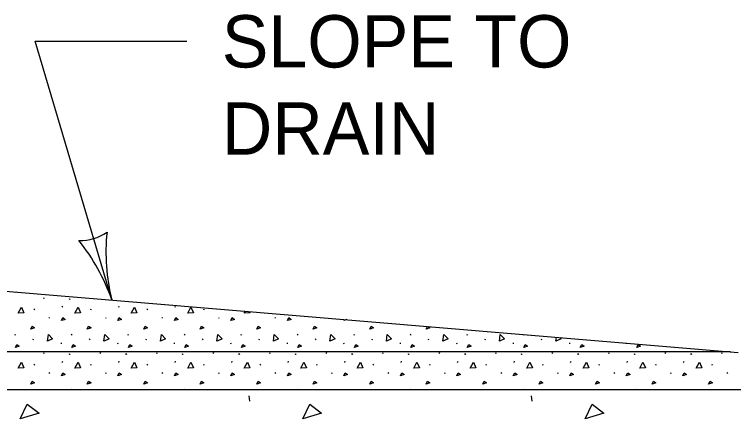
# Model space of a CAD drawing. Extents: x 49991.4 to 50041.6, y 49987.6 to 50011.4.
# Drawn here: x 50026.75 to 50027.575, y 49991.279 to 49991.757 of the extents above; entities that cross this region are included whole.
import ezdxf

# ---------------------------------------------------------------- set-up
doc = ezdxf.new("R2010")
doc.units = 0
for name, color, linetype in [('Level 1', 7, 'Continuous'), ('Level 2', 7, 'Continuous'), ('Level 3', 7, 'Continuous'), ('Level 4', 7, 'Continuous')]:
    doc.layers.add(name, color=color, linetype=linetype)

msp = doc.modelspace()

# ---------------------------------------------------------------- linework, layer by layer
at = {"layer": 'Level 1'}
for p, q in [((50026.14318, 49991.48968), (50027.58032, 49991.36954)), ((50027.01899, 49991.31948), (50027.01967, 49991.31339)), ((50027.34313, 49991.31948), (50027.34381, 49991.31339))]:
    msp.add_line(p, q, dxfattribs=at)
for points in [[(50025.99318, 49991.14695), (50025.99318, 49991.32695), (50027.72873, 49991.32695), (50027.72873, 49991.14695)], [(50026.75661, 49991.29317), (50026.76473, 49991.31009), (50026.77826, 49991.29994), (50026.75661, 49991.29317)], [(50027.08075, 49991.29317), (50027.08887, 49991.31009), (50027.1024, 49991.29994), (50027.08075, 49991.29317)], [(50027.40489, 49991.29317), (50027.41301, 49991.31009), (50027.42654, 49991.29994), (50027.40489, 49991.29317)]]:
    msp.add_lwpolyline(points, dxfattribs=at)
at = {"layer": 'Level 3'}
for p, q in [((50026.86175, 49991.42961), (50026.77384, 49991.72631)), ((50026.77384, 49991.72631), (50026.94792, 49991.72631)), ((50027.57184, 49991.37025), (50026.64808, 49991.37025))]:
    msp.add_line(p, q, dxfattribs=at)
for centre, radius, start, end in [((50026.82532, 49991.55254), 0.05477, 268.64324, 304.3656), ((50027.07733, 49991.48394), 0.22232, 173.96043, 194.14394), ((50026.64189, 49991.35248), 0.233, 19.33173, 38.58158)]:
    msp.add_arc(centre, radius, start, end, dxfattribs=at)
at = {"layer": 'Level 4'}
for p, q in [((50026.7837, 49991.43127), (50026.78424, 49991.43249)), ((50026.81279, 49991.43127), (50026.81333, 49991.43046)), ((50026.81333, 49991.43096), (50026.81388, 49991.43015)), ((50026.80481, 49991.42124), (50026.80535, 49991.42246)), ((50026.86964, 49991.42124), (50026.87018, 49991.42246)), ((50026.93446, 49991.42124), (50026.935, 49991.42246)), ((50026.77273, 49991.41813), (50026.77327, 49991.41935)), ((50026.83756, 49991.41813), (50026.8381, 49991.41935)), ((50026.90239, 49991.41813), (50026.90293, 49991.41935)), ((50026.96722, 49991.41813), (50026.96776, 49991.41935)), ((50026.78965, 49991.40947), (50026.79019, 49991.40865)), ((50026.85448, 49991.40947), (50026.85502, 49991.40865)), ((50026.91931, 49991.40947), (50026.91985, 49991.40865)), ((50026.98413, 49991.40947), (50026.98467, 49991.40865)), ((50027.04896, 49991.40947), (50027.0495, 49991.40865)), ((50026.75081, 49991.3893), (50026.75135, 49991.39052)), ((50026.81564, 49991.3893), (50026.81618, 49991.39052)), ((50026.88046, 49991.3893), (50026.88101, 49991.39052)), ((50026.94529, 49991.3893), (50026.94583, 49991.39052)), ((50027.01012, 49991.3893), (50027.01066, 49991.39052)), ((50027.07495, 49991.3893), (50027.07549, 49991.39052)), ((50027.13977, 49991.3893), (50027.14032, 49991.39052)), ((50027.2046, 49991.3893), (50027.20514, 49991.39052)), ((50027.26943, 49991.3893), (50027.26997, 49991.39052)), ((50027.33426, 49991.3893), (50027.3346, 49991.39008)), ((50026.77138, 49991.38375), (50026.77192, 49991.38497)), ((50026.83621, 49991.38375), (50026.83675, 49991.38497)), ((50026.90104, 49991.38375), (50026.90158, 49991.38497)), ((50026.96586, 49991.38375), (50026.9664, 49991.38497)), ((50027.03069, 49991.38375), (50027.03123, 49991.38497)), ((50027.09552, 49991.38375), (50027.09606, 49991.38497)), ((50027.16035, 49991.38375), (50027.16089, 49991.38497)), ((50027.22517, 49991.38375), (50027.22571, 49991.38497)), ((50027.29, 49991.38375), (50027.29054, 49991.38497)), ((50027.35483, 49991.38375), (50027.35537, 49991.38497)), ((50026.80356, 49991.38035), (50026.80369, 49991.37914)), ((50026.86838, 49991.38035), (50026.86852, 49991.37914)), ((50026.93321, 49991.38035), (50026.93335, 49991.37914)), ((50026.99804, 49991.38035), (50026.99817, 49991.37914)), ((50027.06287, 49991.38035), (50027.063, 49991.37914)), ((50027.12769, 49991.38035), (50027.12783, 49991.37914)), ((50027.19252, 49991.38035), (50027.19266, 49991.37914)), ((50027.25735, 49991.38035), (50027.25748, 49991.37914)), ((50027.32218, 49991.38035), (50027.32231, 49991.37914)), ((50027.387, 49991.38035), (50027.38714, 49991.37914)), ((50027.45184, 49991.38028), (50027.45197, 49991.37914)), ((50026.7837, 49991.36806), (50026.78424, 49991.36927)), ((50026.81279, 49991.36806), (50026.81333, 49991.36724)), ((50026.81333, 49991.36775), (50026.81388, 49991.36693)), ((50026.84852, 49991.36806), (50026.84906, 49991.36927)), ((50026.87762, 49991.36806), (50026.87816, 49991.36724)), ((50026.87816, 49991.36775), (50026.8787, 49991.36693)), ((50026.91335, 49991.36806), (50026.91389, 49991.36927)), ((50026.94245, 49991.36806), (50026.94299, 49991.36724)), ((50026.94299, 49991.36775), (50026.94353, 49991.36693)), ((50026.97818, 49991.36806), (50026.97872, 49991.36927)), ((50027.00728, 49991.36806), (50027.00782, 49991.36724)), ((50027.00782, 49991.36775), (50027.00836, 49991.36693)), ((50027.04301, 49991.36806), (50027.04355, 49991.36927)), ((50027.0721, 49991.36806), (50027.07264, 49991.36724)), ((50027.07264, 49991.36775), (50027.07319, 49991.36693)), ((50027.10783, 49991.36806), (50027.10837, 49991.36927)), ((50027.13693, 49991.36806), (50027.13747, 49991.36724)), ((50027.13747, 49991.36775), (50027.13801, 49991.36693)), ((50027.17266, 49991.36806), (50027.1732, 49991.36927)), ((50027.20176, 49991.36806), (50027.2023, 49991.36724)), ((50027.2023, 49991.36775), (50027.20284, 49991.36693)), ((50027.23749, 49991.36806), (50027.23803, 49991.36927)), ((50027.26659, 49991.36806), (50027.26713, 49991.36724)), ((50027.26713, 49991.36775), (50027.26767, 49991.36693)), ((50027.30232, 49991.36806), (50027.30286, 49991.36927)), ((50027.33141, 49991.36806), (50027.33195, 49991.36724)), ((50027.33195, 49991.36775), (50027.3325, 49991.36693)), ((50027.36714, 49991.36806), (50027.36768, 49991.36927)), ((50027.39624, 49991.36806), (50027.39678, 49991.36724)), ((50027.39678, 49991.36775), (50027.39732, 49991.36693)), ((50027.43197, 49991.36806), (50027.43251, 49991.36927)), ((50027.46107, 49991.36806), (50027.46161, 49991.36724)), ((50027.46161, 49991.36775), (50027.46215, 49991.36693)), ((50027.4968, 49991.36806), (50027.49734, 49991.36927)), ((50027.5259, 49991.36806), (50027.52644, 49991.36724)), ((50027.52644, 49991.36775), (50027.52698, 49991.36693)), ((50027.56163, 49991.36806), (50027.56217, 49991.36927)), ((50026.77273, 49991.35491), (50026.77327, 49991.35613)), ((50026.80481, 49991.35802), (50026.80535, 49991.35924)), ((50026.83756, 49991.35491), (50026.8381, 49991.35613)), ((50026.86964, 49991.35802), (50026.87018, 49991.35924)), ((50026.90239, 49991.35491), (50026.90293, 49991.35613)), ((50026.93446, 49991.35802), (50026.935, 49991.35924)), ((50026.96722, 49991.35491), (50026.96776, 49991.35613)), ((50026.99929, 49991.35802), (50026.99983, 49991.35924)), ((50027.03204, 49991.35491), (50027.03258, 49991.35613)), ((50027.06412, 49991.35802), (50027.06466, 49991.35924)), ((50027.09687, 49991.35491), (50027.09741, 49991.35613)), ((50027.12895, 49991.35802), (50027.12949, 49991.35924)), ((50027.1617, 49991.35491), (50027.16224, 49991.35613)), ((50027.19377, 49991.35802), (50027.19431, 49991.35924)), ((50027.22653, 49991.35491), (50027.22707, 49991.35613)), ((50027.2586, 49991.35802), (50027.25914, 49991.35924)), ((50027.29135, 49991.35491), (50027.29189, 49991.35613)), ((50027.32343, 49991.35802), (50027.32397, 49991.35924)), ((50027.35618, 49991.35491), (50027.35672, 49991.35613)), ((50027.38826, 49991.35802), (50027.3888, 49991.35924)), ((50027.42101, 49991.35491), (50027.42155, 49991.35613)), ((50027.45308, 49991.35802), (50027.45362, 49991.35924)), ((50027.48584, 49991.35491), (50027.48638, 49991.35613)), ((50027.51791, 49991.35802), (50027.51845, 49991.35924)), ((50027.55066, 49991.35491), (50027.5512, 49991.35613)), ((50026.78965, 49991.34625), (50026.79019, 49991.34544)), ((50026.85448, 49991.34625), (50026.85502, 49991.34544)), ((50026.91931, 49991.34625), (50026.91985, 49991.34544)), ((50026.98413, 49991.34625), (50026.98467, 49991.34544)), ((50027.04896, 49991.34625), (50027.0495, 49991.34544)), ((50027.11379, 49991.34625), (50027.11433, 49991.34544)), ((50027.17862, 49991.34625), (50027.17916, 49991.34544)), ((50027.24344, 49991.34625), (50027.24398, 49991.34544)), ((50027.30827, 49991.34625), (50027.30881, 49991.34544)), ((50027.3731, 49991.34625), (50027.37364, 49991.34544)), ((50027.43793, 49991.34625), (50027.43847, 49991.34544)), ((50027.50275, 49991.34625), (50027.50329, 49991.34544)), ((50027.56758, 49991.34625), (50027.56812, 49991.34544)), ((50026.75119, 49991.32695), (50026.75135, 49991.3273)), ((50026.81602, 49991.32695), (50026.81618, 49991.3273)), ((50026.88085, 49991.32695), (50026.88101, 49991.3273)), ((50026.94567, 49991.32695), (50026.94583, 49991.3273)), ((50027.0105, 49991.32695), (50027.01066, 49991.3273)), ((50027.07533, 49991.32695), (50027.07549, 49991.3273)), ((50027.14016, 49991.32695), (50027.14032, 49991.3273)), ((50027.20498, 49991.32695), (50027.20514, 49991.3273)), ((50027.26981, 49991.32695), (50027.26997, 49991.3273)), ((50027.33464, 49991.32695), (50027.3348, 49991.3273)), ((50027.39947, 49991.32695), (50027.39963, 49991.3273)), ((50027.46429, 49991.32695), (50027.46445, 49991.3273)), ((50027.52912, 49991.32695), (50027.52928, 49991.3273))]:
    msp.add_line(p, q, dxfattribs=at)
for points in [[(50026.75108, 49991.43831), (50026.75133, 49991.43884)], [(50026.75247, 49991.43875), (50026.75108, 49991.43831)], [(50026.75446, 49991.41447), (50026.75812, 49991.42138), (50026.76096, 49991.41502), (50026.7546, 49991.41447)], [(50026.81929, 49991.41447), (50026.82294, 49991.42138), (50026.82579, 49991.41502), (50026.81943, 49991.41447)], [(50026.88412, 49991.41447), (50026.88777, 49991.42138), (50026.89061, 49991.41502), (50026.88425, 49991.41447)], [(50026.94895, 49991.41447), (50026.9526, 49991.42138), (50026.95544, 49991.41502), (50026.94908, 49991.41447)], [(50027.01377, 49991.41447), (50027.015, 49991.4168)], [(50027.01965, 49991.41641), (50027.02027, 49991.41502), (50027.01391, 49991.41447)], [(50026.80386, 49991.40595), (50026.80548, 49991.40933), (50026.80819, 49991.4073), (50026.80386, 49991.40595)], [(50026.86869, 49991.40595), (50026.87031, 49991.40933), (50026.87302, 49991.4073), (50026.86869, 49991.40595)], [(50026.93352, 49991.40595), (50026.93514, 49991.40933), (50026.93785, 49991.4073), (50026.93352, 49991.40595)], [(50026.99834, 49991.40595), (50026.99997, 49991.40933), (50027.00267, 49991.4073), (50026.99834, 49991.40595)], [(50027.06317, 49991.40595), (50027.06479, 49991.40933), (50027.0675, 49991.4073), (50027.06317, 49991.40595)], [(50027.128, 49991.40595), (50027.12865, 49991.4073)], [(50027.13155, 49991.40706), (50027.128, 49991.40595)], [(50026.7687, 49991.39627), (50026.77032, 49991.39966), (50026.77303, 49991.39763), (50026.7687, 49991.39627)], [(50026.83353, 49991.39627), (50026.83515, 49991.39966), (50026.83786, 49991.39763), (50026.83353, 49991.39627)], [(50026.89836, 49991.39627), (50026.89998, 49991.39966), (50026.90269, 49991.39763), (50026.89836, 49991.39627)], [(50026.96318, 49991.39627), (50026.96481, 49991.39966), (50026.96751, 49991.39763), (50026.96318, 49991.39627)], [(50027.02801, 49991.39627), (50027.02963, 49991.39966), (50027.03234, 49991.39763), (50027.02801, 49991.39627)], [(50027.09284, 49991.39627), (50027.09446, 49991.39966), (50027.09717, 49991.39763), (50027.09284, 49991.39627)], [(50027.15767, 49991.39627), (50027.15929, 49991.39966), (50027.162, 49991.39763), (50027.15767, 49991.39627)], [(50027.22249, 49991.39627), (50027.22396, 49991.39933)], [(50027.22462, 49991.39928), (50027.22682, 49991.39763), (50027.22249, 49991.39627)], [(50026.78784, 49991.38235), (50026.78892, 49991.39009), (50026.79376, 49991.38508), (50026.78797, 49991.3824)], [(50026.85267, 49991.38235), (50026.85374, 49991.39009), (50026.85859, 49991.38508), (50026.8528, 49991.3824)], [(50026.9175, 49991.38235), (50026.91857, 49991.39009), (50026.92342, 49991.38508), (50026.91763, 49991.3824)], [(50026.98233, 49991.38235), (50026.9834, 49991.39009), (50026.98825, 49991.38508), (50026.98245, 49991.3824)], [(50027.04715, 49991.38235), (50027.04823, 49991.39009), (50027.05307, 49991.38508), (50027.04728, 49991.3824)], [(50027.11198, 49991.38235), (50027.11305, 49991.39009), (50027.1179, 49991.38508), (50027.11211, 49991.3824)], [(50027.17681, 49991.38235), (50027.17788, 49991.39009), (50027.18273, 49991.38508), (50027.17694, 49991.3824)], [(50027.24164, 49991.38235), (50027.24271, 49991.39009), (50027.24756, 49991.38508), (50027.24176, 49991.3824)], [(50027.30646, 49991.38235), (50027.30754, 49991.39009), (50027.31238, 49991.38508), (50027.30659, 49991.3824)], [(50027.37129, 49991.38235), (50027.37193, 49991.38696)], [(50027.3757, 49991.38665), (50027.37721, 49991.38508), (50027.37142, 49991.3824)], [(50026.75108, 49991.37509), (50026.7527, 49991.37848), (50026.75541, 49991.37645), (50026.75108, 49991.37509)], [(50026.81591, 49991.37509), (50026.81753, 49991.37848), (50026.82024, 49991.37645), (50026.81591, 49991.37509)], [(50026.88074, 49991.37509), (50026.88236, 49991.37848), (50026.88507, 49991.37645), (50026.88074, 49991.37509)], [(50026.94556, 49991.37509), (50026.94719, 49991.37848), (50026.94989, 49991.37645), (50026.94556, 49991.37509)], [(50027.01039, 49991.37509), (50027.01201, 49991.37848), (50027.01472, 49991.37645), (50027.01039, 49991.37509)], [(50027.07522, 49991.37509), (50027.07684, 49991.37848), (50027.07955, 49991.37645), (50027.07522, 49991.37509)], [(50027.14005, 49991.37509), (50027.14167, 49991.37848), (50027.14438, 49991.37645), (50027.14005, 49991.37509)], [(50027.20487, 49991.37509), (50027.2065, 49991.37848), (50027.2092, 49991.37645), (50027.20487, 49991.37509)], [(50027.2697, 49991.37509), (50027.27132, 49991.37848), (50027.27403, 49991.37645), (50027.2697, 49991.37509)], [(50027.33453, 49991.37509), (50027.33615, 49991.37848), (50027.33886, 49991.37645), (50027.33453, 49991.37509)], [(50027.39936, 49991.37509), (50027.40098, 49991.37848), (50027.40369, 49991.37645), (50027.39936, 49991.37509)], [(50027.46418, 49991.37509), (50027.46581, 49991.37848), (50027.46851, 49991.37645), (50027.46418, 49991.37509)], [(50026.75446, 49991.35126), (50026.75812, 49991.35816), (50026.76096, 49991.3518), (50026.7546, 49991.35126)], [(50026.81929, 49991.35126), (50026.82294, 49991.35816), (50026.82579, 49991.3518), (50026.81943, 49991.35126)], [(50026.88412, 49991.35126), (50026.88777, 49991.35816), (50026.89061, 49991.3518), (50026.88425, 49991.35126)], [(50026.94895, 49991.35126), (50026.9526, 49991.35816), (50026.95544, 49991.3518), (50026.94908, 49991.35126)], [(50027.01377, 49991.35126), (50027.01743, 49991.35816), (50027.02027, 49991.3518), (50027.01391, 49991.35126)], [(50027.0786, 49991.35126), (50027.08225, 49991.35816), (50027.0851, 49991.3518), (50027.07874, 49991.35126)], [(50027.14343, 49991.35126), (50027.14708, 49991.35816), (50027.14992, 49991.3518), (50027.14356, 49991.35126)], [(50027.20826, 49991.35126), (50027.21191, 49991.35816), (50027.21475, 49991.3518), (50027.20839, 49991.35126)], [(50027.27308, 49991.35126), (50027.27674, 49991.35816), (50027.27958, 49991.3518), (50027.27322, 49991.35126)], [(50027.33791, 49991.35126), (50027.34156, 49991.35816), (50027.34441, 49991.3518), (50027.33805, 49991.35126)], [(50027.40274, 49991.35126), (50027.40639, 49991.35816), (50027.40923, 49991.3518), (50027.40287, 49991.35126)], [(50027.46757, 49991.35126), (50027.47122, 49991.35816), (50027.47406, 49991.3518), (50027.4677, 49991.35126)], [(50027.53239, 49991.35126), (50027.53605, 49991.35816), (50027.53889, 49991.3518), (50027.53253, 49991.35126)], [(50026.80386, 49991.34273), (50026.80548, 49991.34611), (50026.80819, 49991.34408), (50026.80386, 49991.34273)], [(50026.86869, 49991.34273), (50026.87031, 49991.34611), (50026.87302, 49991.34408), (50026.86869, 49991.34273)], [(50026.93352, 49991.34273), (50026.93514, 49991.34611), (50026.93785, 49991.34408), (50026.93352, 49991.34273)], [(50026.99834, 49991.34273), (50026.99997, 49991.34611), (50027.00267, 49991.34408), (50026.99834, 49991.34273)], [(50027.06317, 49991.34273), (50027.06479, 49991.34611), (50027.0675, 49991.34408), (50027.06317, 49991.34273)], [(50027.128, 49991.34273), (50027.12962, 49991.34611), (50027.13233, 49991.34408), (50027.128, 49991.34273)], [(50027.19283, 49991.34273), (50027.19445, 49991.34611), (50027.19716, 49991.34408), (50027.19283, 49991.34273)], [(50027.25765, 49991.34273), (50027.25928, 49991.34611), (50027.26198, 49991.34408), (50027.25765, 49991.34273)], [(50027.32248, 49991.34273), (50027.3241, 49991.34611), (50027.32681, 49991.34408), (50027.32248, 49991.34273)], [(50027.38731, 49991.34273), (50027.38893, 49991.34611), (50027.39164, 49991.34408), (50027.38731, 49991.34273)], [(50027.45214, 49991.34273), (50027.45376, 49991.34611), (50027.45647, 49991.34408), (50027.45214, 49991.34273)], [(50027.51696, 49991.34273), (50027.51859, 49991.34611), (50027.52129, 49991.34408), (50027.51696, 49991.34273)], [(50026.7687, 49991.33306), (50026.77032, 49991.33644), (50026.77303, 49991.33441), (50026.7687, 49991.33306)], [(50026.83353, 49991.33306), (50026.83515, 49991.33644), (50026.83786, 49991.33441), (50026.83353, 49991.33306)], [(50026.89836, 49991.33306), (50026.89998, 49991.33644), (50026.90269, 49991.33441), (50026.89836, 49991.33306)], [(50026.96318, 49991.33306), (50026.96481, 49991.33644), (50026.96751, 49991.33441), (50026.96318, 49991.33306)], [(50027.02801, 49991.33306), (50027.02963, 49991.33644), (50027.03234, 49991.33441), (50027.02801, 49991.33306)], [(50027.09284, 49991.33306), (50027.09446, 49991.33644), (50027.09717, 49991.33441), (50027.09284, 49991.33306)], [(50027.15767, 49991.33306), (50027.15929, 49991.33644), (50027.162, 49991.33441), (50027.15767, 49991.33306)], [(50027.22249, 49991.33306), (50027.22412, 49991.33644), (50027.22682, 49991.33441), (50027.22249, 49991.33306)], [(50027.28732, 49991.33306), (50027.28894, 49991.33644), (50027.29165, 49991.33441), (50027.28732, 49991.33306)], [(50027.35215, 49991.33306), (50027.35377, 49991.33644), (50027.35648, 49991.33441), (50027.35215, 49991.33306)], [(50027.41698, 49991.33306), (50027.4186, 49991.33644), (50027.42131, 49991.33441), (50027.41698, 49991.33306)], [(50027.4818, 49991.33306), (50027.48343, 49991.33644), (50027.48613, 49991.33441), (50027.4818, 49991.33306)], [(50027.54663, 49991.33306), (50027.54825, 49991.33644), (50027.55096, 49991.33441), (50027.54663, 49991.33306)]]:
    msp.add_lwpolyline(points, dxfattribs=at)

# ---------------------------------------------------------------- texts
at = {"layer": 'Level 2'}
for s, p in [('SLOPE TO', (50026.98792, 49991.69631)), ('DRAIN', (50026.98792, 49991.59631))]:
    msp.add_text(s, height=0.06, rotation=360, dxfattribs=at).set_placement(p)

doc.saveas('drawing.dxf')
